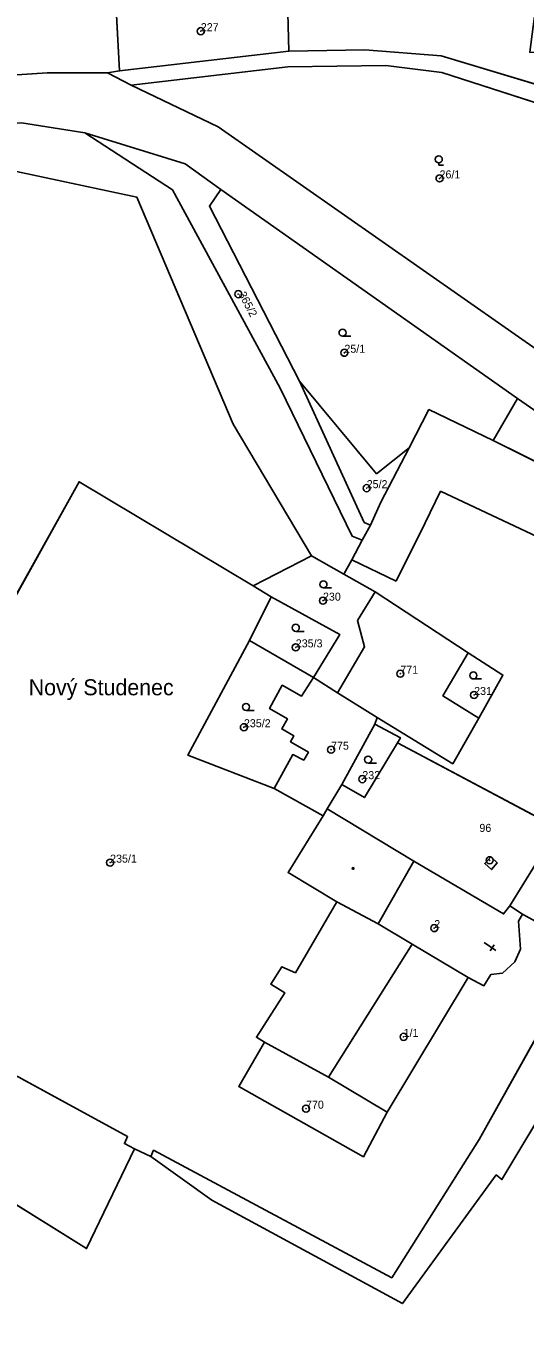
# Model space of a CAD drawing. Extents: x -652854 to -650068, y -1097661 to -1095417.
# Drawn here: x -651110.6 to -651004.4, y -1096137.1 to -1095861.8 of the extents above; entities that cross this region are included whole.
import ezdxf

# ---------------------------------------------------------------- set-up
doc = ezdxf.new("R2010")
doc.units = 0
for name, color, linetype in [('Definiční body parcel', 7, 'Continuous'), ('Hranice - vnitř_ kresba', 7, 'Continuous'), ('Hranice parcel', 7, 'Continuous'), ('Obvody jako plochy', 7, 'Continuous'), ('Ostatní mapové značky 1', 7, 'Continuous'), ('Parcelní čísla', 7, 'Continuous'), ('Prvky pro prodl_ par_ č_', 7, 'Continuous'), ('Značky kultur', 7, 'Continuous'), ('Značky na budově ne v SPI', 7, 'Continuous')]:
    doc.layers.add(name, color=color, linetype=linetype)

msp = doc.modelspace()

# ---------------------------------------------------------------- linework, layer by layer
at = {"layer": 'Definiční body parcel'}
for centre, radius in [((-651073.37, -1095862.89), 0.75), ((-651073.37, -1095862.89), 0.0327), ((-651022.6, -1095894.16), 0.75), ((-651022.6, -1095894.16), 0.0327), ((-651065.4, -1095918.74), 0.75), ((-651065.4, -1095918.74), 0.0327), ((-651042.83, -1095931.19), 0.75), ((-651042.83, -1095931.19), 0.0327), ((-651038.09, -1095959.95), 0.75), ((-651038.09, -1095959.95), 0.0327), ((-651047.39, -1095983.84), 0.75), ((-651047.39, -1095983.84), 0.0327), ((-651053.17, -1095993.76), 0.75), ((-651053.17, -1095993.76), 0.0327), ((-651030.94, -1095999.36), 0.75), ((-651030.94, -1095999.36), 0.0327), ((-651015.24, -1096003.87), 0.75), ((-651015.24, -1096003.87), 0.0327), ((-651064.2, -1096010.72), 0.75), ((-651064.2, -1096010.72), 0.0327), ((-651045.66, -1096015.5), 0.75), ((-651045.66, -1096015.5), 0.0327), ((-651039.02, -1096021.75), 0.75), ((-651039.02, -1096021.75), 0.0327), ((-651092.65, -1096039.48), 0.75), ((-651092.65, -1096039.48), 0.0327), ((-651011.94, -1096038.97), 0.75), ((-651011.94, -1096038.97), 0.0327), ((-651023.72, -1096053.39), 0.75), ((-651023.72, -1096053.39), 0.0327), ((-651030.24, -1096076.48), 0.75), ((-651030.24, -1096076.48), 0.0327), ((-651050.99, -1096091.73), 0.75), ((-651050.99, -1096091.73), 0.0327)]:
    msp.add_circle(centre, radius, dxfattribs=at)
at = {"layer": 'Hranice - vnitř_ kresba'}
for p, q in [((-651022.36, -1095960.61), (-651025.62, -1095967.28)), ((-650974.45, -1095983.2), (-651022.36, -1095960.61)), ((-651025.62, -1095967.28), (-651031.82, -1095979.67)), ((-651031.82, -1095979.67), (-651041.27, -1095975.19)), ((-651028.03, -1096039.18), (-651046.49, -1096028.08)), ((-651035.68, -1096052.5), (-651044.45, -1096047.83)), ((-651046.21, -1096085.02), (-651028.45, -1096056.8))]:
    msp.add_line(p, q, dxfattribs=at)
at = {"layer": 'Hranice parcel'}
for p, q in [((-651090.63, -1095871.34), (-651091.53, -1095855.39)), ((-651054.94, -1095856.32), (-651054.66, -1095867.16)), ((-651054.66, -1095867.16), (-651090.63, -1095871.34)), ((-651038.51, -1095866.83), (-651054.66, -1095867.16)), ((-651022.27, -1095868.13), (-651038.51, -1095866.83)), ((-650974.96, -1095882.35), (-651022.27, -1095868.13)), ((-651093.24, -1095871.75), (-651090.63, -1095871.34)), ((-651088.16, -1095874.33), (-651054.86, -1095870.49)), ((-651054.86, -1095870.49), (-651034.02, -1095870.19)), ((-651034.02, -1095870.19), (-651022.11, -1095871.64)), ((-651124.53, -1095872.94), (-651106.05, -1095871.75)), ((-651106.05, -1095871.75), (-651093.24, -1095871.75)), ((-651093.24, -1095871.75), (-651088.16, -1095874.33)), ((-651088.16, -1095874.33), (-651069.69, -1095883.2)), ((-651022.11, -1095871.64), (-650984.48, -1095883.78)), ((-651111.53, -1095882.37), (-651098.01, -1095884.51)), ((-651098.01, -1095884.51), (-651076.72, -1095891.08)), ((-651079.41, -1095896.61), (-651098.01, -1095884.51)), ((-650999.89, -1095931.88), (-651069.69, -1095883.2)), ((-651086.96, -1095898.16), (-651112.56, -1095892.68)), ((-651076.72, -1095891.08), (-651069.09, -1095896.55)), ((-651066.45, -1095946.35), (-651086.96, -1095898.16)), ((-651056.46, -1095938.68), (-651079.41, -1095896.61)), ((-651071.53, -1095900.06), (-651069.09, -1095896.55)), ((-651069.09, -1095896.55), (-651006, -1095940.92)), ((-651052.4, -1095937.19), (-651071.53, -1095900.06)), ((-651035.98, -1095956.89), (-651052.4, -1095937.19)), ((-651038.62, -1095967.24), (-651052.4, -1095937.19)), ((-651041.17, -1095970.17), (-651056.46, -1095938.68)), ((-651006, -1095940.92), (-651011.17, -1095949.81)), ((-651006, -1095940.92), (-650970.52, -1095965.45)), ((-651024.87, -1095943.25), (-651029.07, -1095951.36)), ((-651011.17, -1095949.81), (-651024.87, -1095943.25)), ((-651049.83, -1095974.3), (-651066.45, -1095946.35)), ((-651029.07, -1095951.36), (-651035.98, -1095956.89)), ((-651029.07, -1095951.36), (-651035.05, -1095962.91)), ((-651011.17, -1095949.81), (-650968.76, -1095970.97)), ((-651099.24, -1095958.6), (-651156.45, -1096060.87)), ((-651062.2, -1095980.68), (-651099.24, -1095958.6)), ((-651035.05, -1095962.91), (-651037.29, -1095967.84)), ((-651037.29, -1095967.84), (-651039.04, -1095970.98)), ((-651037.29, -1095967.84), (-651038.62, -1095967.24)), ((-651039.04, -1095970.98), (-651041.17, -1095970.17)), ((-651039.04, -1095970.98), (-651041.27, -1095975.19)), ((-651049.83, -1095974.3), (-651062.2, -1095980.68)), ((-651042.95, -1095978.23), (-651049.83, -1095974.3)), ((-651041.27, -1095975.19), (-651042.95, -1095978.23)), ((-651042.95, -1095978.23), (-651036.31, -1095981.99)), ((-651062.2, -1095980.68), (-651058.42, -1095983)), ((-651062.99, -1095992.32), (-651058.42, -1095983)), ((-651058.42, -1095983), (-651043.8, -1095991.06)), ((-651036.31, -1095981.99), (-651040.01, -1095988.02)), ((-651016.51, -1095994.93), (-651036.31, -1095981.99)), ((-651040.01, -1095988.02), (-651038.52, -1095993.63)), ((-651062.99, -1095992.32), (-651076.09, -1096016.68)), ((-651049.38, -1096000.16), (-651062.99, -1095992.32)), ((-651043.8, -1095991.06), (-651049.38, -1096000.16)), ((-651038.52, -1095993.63), (-651044.31, -1096003.39)), ((-651021.89, -1096004.07), (-651016.51, -1095994.93)), ((-651016.51, -1095994.93), (-651009.12, -1095999.65)), ((-651051.97, -1096004.15), (-651049.38, -1096000.16)), ((-651049.38, -1096000.16), (-651044.31, -1096003.39)), ((-651009.12, -1095999.65), (-651014.21, -1096008.81)), ((-651058.74, -1096006.76), (-651056.05, -1096001.82)), ((-651056.05, -1096001.82), (-651051.97, -1096004.15)), ((-651044.31, -1096003.39), (-651035.85, -1096008.64)), ((-651014.21, -1096008.81), (-651021.89, -1096004.07)), ((-651054.93, -1096008.96), (-651058.74, -1096006.76)), ((-651056.17, -1096011.09), (-651054.93, -1096008.96)), ((-651035.85, -1096008.64), (-651036.33, -1096010.06)), ((-651035.85, -1096008.64), (-651019.78, -1096018.47)), ((-651019.78, -1096018.47), (-651014.21, -1096008.81)), ((-651053.57, -1096012.57), (-651056.17, -1096011.09)), ((-651036.33, -1096010.06), (-651043.36, -1096022.88)), ((-651036.33, -1096010.06), (-651030.93, -1096012.97)), ((-651054.31, -1096013.79), (-651053.57, -1096012.57)), ((-651050.48, -1096016.04), (-651054.31, -1096013.79)), ((-651031.54, -1096014.05), (-651038.59, -1096025.68)), ((-651030.93, -1096012.97), (-651031.54, -1096014.05)), ((-650997.45, -1096032.13), (-651031.54, -1096014.05)), ((-651076.09, -1096016.68), (-651057.79, -1096023.76)), ((-651057.79, -1096023.76), (-651053.82, -1096016.53)), ((-651053.82, -1096016.53), (-651051.47, -1096017.69)), ((-651051.47, -1096017.69), (-651050.48, -1096016.04)), ((-651043.36, -1096022.88), (-651046.49, -1096028.08)), ((-651038.59, -1096025.68), (-651043.36, -1096022.88)), ((-651047.38, -1096029.56), (-651057.79, -1096023.76)), ((-651046.49, -1096028.08), (-651047.38, -1096029.56)), ((-651047.38, -1096029.56), (-651054.82, -1096041.58)), ((-651007.66, -1096048.68), (-650997.45, -1096032.13)), ((-651028.03, -1096039.18), (-651035.68, -1096052.5)), ((-651008.97, -1096050.36), (-651028.03, -1096039.18)), ((-651011.72, -1096038.27), (-651012.99, -1096039.68)), ((-651010.31, -1096039.54), (-651011.72, -1096038.27)), ((-651054.82, -1096041.58), (-651044.45, -1096047.83)), ((-651012.99, -1096039.68), (-651011.58, -1096040.95)), ((-651011.58, -1096040.95), (-651010.31, -1096039.54)), ((-651044.45, -1096047.83), (-651053.23, -1096062.86)), ((-651007.66, -1096048.68), (-651008.97, -1096050.36)), ((-651004.94, -1096050.45), (-651007.66, -1096048.68)), ((-651005.78, -1096051.88), (-651004.94, -1096050.45)), ((-651004.94, -1096050.45), (-650991.56, -1096057.81)), ((-651035.68, -1096052.5), (-651028.45, -1096056.8)), ((-651005.39, -1096057.83), (-651005.78, -1096051.88)), ((-651028.45, -1096056.8), (-651016.5, -1096063.88)), ((-651014.14, -1096098.31), (-650991.56, -1096057.81)), ((-651006.56, -1096060.52), (-651005.39, -1096057.83)), ((-651156.45, -1096060.87), (-651088.94, -1096097.65)), ((-651009.19, -1096062.94), (-651006.56, -1096060.52)), ((-651056.1, -1096061.61), (-651058.49, -1096065.31)), ((-651053.23, -1096062.86), (-651056.1, -1096061.61)), ((-651033.7, -1096092.48), (-651016.5, -1096063.88)), ((-651016.5, -1096063.88), (-651013.15, -1096065.63)), ((-651013.15, -1096065.63), (-651011.7, -1096063.27)), ((-651011.7, -1096063.27), (-651009.19, -1096062.94)), ((-651058.49, -1096065.31), (-651055.5, -1096067.11)), ((-651055.5, -1096067.11), (-651061.54, -1096076.57)), ((-651059.8, -1096077.59), (-651065.3, -1096087.03)), ((-651061.54, -1096076.57), (-651059.8, -1096077.59)), ((-651059.8, -1096077.59), (-651046.21, -1096085.02)), ((-651009.35, -1096106.79), (-650990.95, -1096076.09)), ((-651165.97, -1096079.02), (-651097.64, -1096121.44)), ((-651046.21, -1096085.02), (-651033.7, -1096092.48)), ((-651065.3, -1096087.03), (-651038.78, -1096101.94)), ((-651038.78, -1096101.94), (-651033.7, -1096092.48)), ((-651088.94, -1096097.65), (-651089.62, -1096099.14)), ((-651089.62, -1096099.14), (-651087.49, -1096100.27)), ((-651032.76, -1096127.64), (-651014.14, -1096098.31)), ((-651097.64, -1096121.44), (-651087.49, -1096100.27)), ((-651087.49, -1096100.27), (-651084.01, -1096101.86)), ((-651084.01, -1096101.86), (-651083.41, -1096100.58)), ((-651084.01, -1096101.86), (-651070.99, -1096111.17)), ((-651083.41, -1096100.58), (-651032.76, -1096127.64)), ((-651030.5, -1096133.13), (-651010.55, -1096105.82)), ((-651010.55, -1096105.82), (-651009.35, -1096106.79)), ((-651070.99, -1096111.17), (-651030.5, -1096133.13))]:
    msp.add_line(p, q, dxfattribs=at)
at = {"layer": 'Obvody jako plochy'}
for points in [[(-651124.53, -1095872.94), (-651106.05, -1095871.75), (-651093.24, -1095871.75), (-651090.63, -1095871.34), (-651091.53, -1095855.39), (-651091.66, -1095853.64), (-651099.73, -1095851.59), (-651143.81, -1095850.45), (-651170.03, -1095857.03), (-651182.24, -1095863.72), (-651181.83, -1095868.33), (-651181.14, -1095876.14)], [(-651054.94, -1095856.32), (-651091.53, -1095855.39), (-651090.63, -1095871.34), (-651054.66, -1095867.16)], [(-651034.02, -1095870.19), (-651054.86, -1095870.49), (-651088.16, -1095874.33), (-651069.69, -1095883.2), (-650999.89, -1095931.88), (-650991.01, -1095904.42), (-650984.48, -1095883.78), (-651022.11, -1095871.64)], [(-651076.72, -1095891.08), (-651098.01, -1095884.51), (-651079.41, -1095896.61), (-651056.46, -1095938.68), (-651041.17, -1095970.17), (-651039.04, -1095970.98), (-651037.29, -1095967.84), (-651038.62, -1095967.24), (-651052.4, -1095937.19), (-651071.53, -1095900.06), (-651069.09, -1095896.55)], [(-651069.09, -1095896.55), (-651071.53, -1095900.06), (-651052.4, -1095937.19), (-651035.98, -1095956.89), (-651029.07, -1095951.36), (-651024.87, -1095943.25), (-651011.17, -1095949.81), (-651006, -1095940.92)], [(-651029.07, -1095951.36), (-651035.98, -1095956.89), (-651052.4, -1095937.19), (-651038.62, -1095967.24), (-651037.29, -1095967.84), (-651035.05, -1095962.91)], [(-651006, -1095940.92), (-651011.17, -1095949.81), (-650968.76, -1095970.97), (-650956.46, -1095986.73), (-650946.25, -1095992.54), (-650943.99, -1095992.27), (-650941.58, -1095987.24), (-650947.06, -1095985.27), (-650970.52, -1095965.45)], [(-651099.24, -1095958.6), (-651156.45, -1096060.87), (-651088.94, -1096097.65), (-651089.62, -1096099.14), (-651087.49, -1096100.27), (-651084.01, -1096101.86), (-651083.41, -1096100.58), (-651032.76, -1096127.64), (-651014.14, -1096098.31), (-650991.56, -1096057.81), (-651004.94, -1096050.45), (-651005.78, -1096051.88), (-651005.39, -1096057.83), (-651006.56, -1096060.52), (-651009.19, -1096062.94), (-651011.7, -1096063.27), (-651013.15, -1096065.63), (-651016.5, -1096063.88), (-651033.7, -1096092.48), (-651038.78, -1096101.94), (-651065.3, -1096087.03), (-651059.8, -1096077.59), (-651061.54, -1096076.57), (-651055.5, -1096067.11), (-651058.49, -1096065.31), (-651056.1, -1096061.61), (-651053.23, -1096062.86), (-651044.45, -1096047.83), (-651054.82, -1096041.58), (-651047.38, -1096029.56), (-651057.79, -1096023.76), (-651076.09, -1096016.68), (-651062.99, -1095992.32), (-651058.42, -1095983), (-651062.2, -1095980.68)], [(-651042.95, -1095978.23), (-651049.83, -1095974.3), (-651062.2, -1095980.68), (-651058.42, -1095983), (-651043.8, -1095991.06), (-651049.38, -1096000.16), (-651044.31, -1096003.39), (-651038.52, -1095993.63), (-651040.01, -1095988.02), (-651036.31, -1095981.99)], [(-651062.99, -1095992.32), (-651049.38, -1096000.16), (-651043.8, -1095991.06), (-651058.42, -1095983)], [(-651036.31, -1095981.99), (-651040.01, -1095988.02), (-651038.52, -1095993.63), (-651044.31, -1096003.39), (-651035.85, -1096008.64), (-651019.78, -1096018.47), (-651014.21, -1096008.81), (-651021.89, -1096004.07), (-651016.51, -1095994.93)], [(-651049.38, -1096000.16), (-651062.99, -1095992.32), (-651076.09, -1096016.68), (-651057.79, -1096023.76), (-651053.82, -1096016.53), (-651051.47, -1096017.69), (-651050.48, -1096016.04), (-651054.31, -1096013.79), (-651053.57, -1096012.57), (-651056.17, -1096011.09), (-651054.93, -1096008.96), (-651058.74, -1096006.76), (-651056.05, -1096001.82), (-651051.97, -1096004.15)], [(-651021.89, -1096004.07), (-651014.21, -1096008.81), (-651009.12, -1095999.65), (-651016.51, -1095994.93)], [(-651044.31, -1096003.39), (-651049.38, -1096000.16), (-651051.97, -1096004.15), (-651056.05, -1096001.82), (-651058.74, -1096006.76), (-651054.93, -1096008.96), (-651056.17, -1096011.09), (-651053.57, -1096012.57), (-651054.31, -1096013.79), (-651050.48, -1096016.04), (-651051.47, -1096017.69), (-651053.82, -1096016.53), (-651057.79, -1096023.76), (-651047.38, -1096029.56), (-651046.49, -1096028.08), (-651043.36, -1096022.88), (-651036.33, -1096010.06), (-651035.85, -1096008.64)], [(-651031.54, -1096014.05), (-651030.93, -1096012.97), (-651036.33, -1096010.06), (-651043.36, -1096022.88), (-651038.59, -1096025.68)], [(-651031.54, -1096014.05), (-651038.59, -1096025.68), (-651043.36, -1096022.88), (-651046.49, -1096028.08), (-651047.38, -1096029.56), (-651054.82, -1096041.58), (-651044.45, -1096047.83), (-651053.23, -1096062.86), (-651056.1, -1096061.61), (-651058.49, -1096065.31), (-651055.5, -1096067.11), (-651061.54, -1096076.57), (-651059.8, -1096077.59), (-651046.21, -1096085.02), (-651033.7, -1096092.48), (-651016.5, -1096063.88), (-651028.45, -1096056.8), (-651035.68, -1096052.5), (-651028.03, -1096039.18), (-651008.97, -1096050.36), (-651007.66, -1096048.68), (-650997.45, -1096032.13)], [(-650991.56, -1096057.81), (-651014.14, -1096098.31), (-651032.76, -1096127.64), (-651083.41, -1096100.58), (-651084.01, -1096101.86), (-651070.99, -1096111.17), (-651030.5, -1096133.13), (-651010.55, -1096105.82), (-651009.35, -1096106.79), (-650990.95, -1096076.09), (-650976.4, -1096052.35), (-650958.9, -1096023.69), (-650965.14, -1096019.73), (-650974.42, -1096033.09), (-650976.56, -1096031.8), (-650981.53, -1096040.37)], [(-651004.94, -1096050.45), (-650991.56, -1096057.81), (-650981.53, -1096040.37), (-650997.45, -1096032.13), (-651007.66, -1096048.68)], [(-651016.5, -1096063.88), (-651013.15, -1096065.63), (-651011.7, -1096063.27), (-651009.19, -1096062.94), (-651006.56, -1096060.52), (-651005.39, -1096057.83), (-651005.78, -1096051.88), (-651004.94, -1096050.45), (-651007.66, -1096048.68), (-651008.97, -1096050.36), (-651028.03, -1096039.18), (-651035.68, -1096052.5), (-651028.45, -1096056.8)], [(-651011.72, -1096038.27), (-651010.31, -1096039.54), (-651011.58, -1096040.95), (-651012.99, -1096039.68)], [(-651011.72, -1096038.27), (-651012.99, -1096039.68), (-651011.58, -1096040.95), (-651010.31, -1096039.54)], [(-651156.45, -1096060.87), (-651165.97, -1096079.02), (-651097.64, -1096121.44), (-651087.49, -1096100.27), (-651089.62, -1096099.14), (-651088.94, -1096097.65)], [(-651059.8, -1096077.59), (-651065.3, -1096087.03), (-651038.78, -1096101.94), (-651033.7, -1096092.48), (-651046.21, -1096085.02)]]:
    msp.add_lwpolyline(points, close=True, dxfattribs=at)
for points in [[(-651054.94, -1095856.32), (-651054.66, -1095867.16), (-651038.51, -1095866.83), (-651022.27, -1095868.13), (-650974.96, -1095882.35), (-650973.58, -1095873.61), (-650988.14, -1095868.33), (-650989.22, -1095874.08), (-650991.88, -1095873.74), (-650991.37, -1095868.09), (-650996.85, -1095867.76), (-651003.42, -1095867.37), (-651001.98, -1095856.46)], [(-650974.96, -1095882.35), (-651022.27, -1095868.13), (-651038.51, -1095866.83), (-651054.66, -1095867.16), (-651090.63, -1095871.34), (-651093.24, -1095871.75), (-651088.16, -1095874.33), (-651054.86, -1095870.49), (-651034.02, -1095870.19), (-651022.11, -1095871.64), (-650984.48, -1095883.78)], [(-650815.91, -1096079.94), (-650837.43, -1096057.82), (-650851.49, -1096042.56), (-650856.61, -1096037.55), (-650866.08, -1096025.56), (-650869.83, -1096021.1), (-650878.58, -1096010.13), (-650884.15, -1096004.16), (-650888.72, -1095999.9), (-650906.97, -1095987.24), (-650919.07, -1095983.1), (-650939.79, -1095976.94), (-650942.73, -1095975.31), (-650965.11, -1095955.28), (-650999.89, -1095931.88), (-651069.69, -1095883.2), (-651088.16, -1095874.33), (-651093.24, -1095871.75), (-651106.05, -1095871.75), (-651124.53, -1095872.94)], [(-651301.18, -1095941.4), (-651256.73, -1095919.7), (-651224.65, -1095909.2), (-651141.79, -1095892.88), (-651112.56, -1095892.68), (-651086.96, -1095898.16), (-651066.45, -1095946.35), (-651049.83, -1095974.3), (-651042.95, -1095978.23), (-651041.27, -1095975.19), (-651039.04, -1095970.98), (-651041.17, -1095970.17), (-651056.46, -1095938.68), (-651079.41, -1095896.61), (-651098.01, -1095884.51), (-651111.53, -1095882.37), (-651143.77, -1095884.53), (-651179.53, -1095886.51), (-651245.57, -1095889.73), (-651286.04, -1095900.87), (-651326.79, -1095933.01)], [(-651111.53, -1095882.37), (-651098.01, -1095884.51), (-651076.72, -1095891.08), (-651069.09, -1095896.55), (-651006, -1095940.92), (-650970.52, -1095965.45), (-650947.06, -1095985.27), (-650941.58, -1095987.24), (-650928.95, -1095991.79), (-650910.04, -1095998.66), (-650895.24, -1096007.92), (-650885.14, -1096017.44), (-650874.29, -1096030.48), (-650868.81, -1096038.2), (-650844.12, -1096064.27), (-650836.01, -1096073.17), (-650788.5, -1096124.42)], [(-650933.62, -1096190.95), (-650913.45, -1096134.6), (-650990.95, -1096076.09), (-651009.35, -1096106.79), (-651010.55, -1096105.82), (-651030.5, -1096133.13), (-651070.99, -1096111.17), (-651084.01, -1096101.86), (-651087.49, -1096100.27), (-651097.64, -1096121.44), (-651165.97, -1096079.02), (-651156.45, -1096060.87), (-651099.24, -1095958.6), (-651062.2, -1095980.68), (-651049.83, -1095974.3), (-651066.45, -1095946.35), (-651086.96, -1095898.16), (-651112.56, -1095892.68), (-651141.79, -1095892.88), (-651224.65, -1095909.2), (-651256.73, -1095919.7), (-651301.18, -1095941.4)], [(-650968.76, -1095970.97), (-651011.17, -1095949.81), (-651024.87, -1095943.25), (-651029.07, -1095951.36), (-651035.05, -1095962.91), (-651037.29, -1095967.84), (-651039.04, -1095970.98), (-651041.27, -1095975.19), (-651042.95, -1095978.23), (-651036.31, -1095981.99), (-651016.51, -1095994.93), (-651009.12, -1095999.65), (-651014.21, -1096008.81), (-651019.78, -1096018.47), (-651035.85, -1096008.64), (-651036.33, -1096010.06), (-651030.93, -1096012.97), (-651031.54, -1096014.05), (-650997.45, -1096032.13)]]:
    msp.add_lwpolyline(points, dxfattribs=at)
at = {"layer": 'Ostatní mapové značky 1'}
for p, q in [((-651013.08, -1096056.46), (-651010.597, -1096058.143)), ((-651011.845, -1096058.203), (-651011.004, -1096056.961))]:
    msp.add_line(p, q, dxfattribs=at)
at = {"layer": 'Značky kultur'}
for p, q in [((-651022.76, -1095890.86), (-651022.76, -1095891.36)), ((-651022.76, -1095891.36), (-651021.737, -1095891.36)), ((-651041.47, -1095927.69), (-651043.22, -1095927.69)), ((-651045.54, -1095981.14), (-651047.29, -1095981.14)), ((-651051.42, -1095990.36), (-651053.17, -1095990.36)), ((-651013.65, -1096000.47), (-651015.4, -1096000.47)), ((-651061.99, -1096007.16), (-651063.74, -1096007.16)), ((-651036.03, -1096018.35), (-651037.78, -1096018.35))]:
    msp.add_line(p, q, dxfattribs=at)
for centre in [(-651022.76, -1095890.11), (-651043.22, -1095926.94), (-651047.29, -1095980.39), (-651053.17, -1095989.61), (-651015.4, -1095999.72), (-651063.74, -1096006.41), (-651037.78, -1096017.6)]:
    msp.add_circle(centre, 0.75, dxfattribs=at)
at = {"layer": 'Značky na budově ne v SPI'}
msp.add_circle((-651040.97, -1096040.72), 0.175, dxfattribs=at)

# ---------------------------------------------------------------- texts
at = {"layer": 'Obvody jako plochy'}
msp.add_text('Nový Studenec', height=3.4, dxfattribs=at).set_placement((-651109.97, -1096003.94))
at = {"layer": 'Parcelní čísla'}
for s, height, p in [('227', 1.7, (-651073.37, -1095862.89)), ('26/1', 1.7, (-651022.6, -1095894.16)), ('25/1', 1.7, (-651042.83, -1095931.19)), ('25/2', 1.7, (-651038.09, -1095959.95)), ('230', 1.7, (-651047.39, -1095983.84)), ('235/3', 1.7, (-651053.17, -1095993.76)), ('771', 1.7, (-651030.94, -1095999.36)), ('231', 1.7, (-651015.24, -1096003.87)), ('235/2', 1.7, (-651064.2, -1096010.72)), ('775', 1.7, (-651045.66, -1096015.5)), ('232', 1.7, (-651039.02, -1096021.75)), ('235/1', 1.7, (-651092.65, -1096039.48)), ('96', 0.1, (-651011.94, -1096038.97)), ('2', 1.7, (-651023.72, -1096053.39)), ('1/1', 1.7, (-651030.24, -1096076.48)), ('770', 1.7, (-651050.99, -1096091.73))]:
    msp.add_text(s, height=height, dxfattribs=at).set_placement(p)
msp.add_text('365/2', height=1.7, rotation=297.603, dxfattribs=at).set_placement((-651065.4, -1095918.74))
at = {"layer": 'Prvky pro prodl_ par_ č_'}
msp.add_text('96', height=1.7, dxfattribs=at).set_placement((-651014.12, -1096032.95))

doc.saveas('drawing.dxf')
